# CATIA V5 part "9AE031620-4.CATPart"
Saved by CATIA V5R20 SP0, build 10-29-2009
Part number: 9AE031620-4
Revision: ANY
Definition: UNKNOWN
Nomenclature: 9AE031620-4
Source: Unknown
Bounding box of the stored display mesh (mm): x -3.679 to 3.679, y -3.679 to 3.679, z 0 to 12.6
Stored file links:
  C:\Users\Utente\Desktop\IO LAVORO\3D X SITO CF\CUMSA\3D files AE\AE 031620\9AE031620-4.CATPart
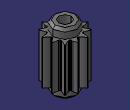
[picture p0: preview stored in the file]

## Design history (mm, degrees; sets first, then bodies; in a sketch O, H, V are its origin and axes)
Body1 "Chaflán1" (main body)
  Solid1: solid without history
